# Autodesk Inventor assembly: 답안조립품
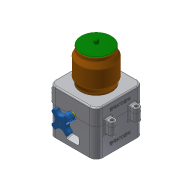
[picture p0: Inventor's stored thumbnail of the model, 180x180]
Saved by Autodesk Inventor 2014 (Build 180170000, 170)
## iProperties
Created: 2018-01
Part Number: 답안조립품
Document SubType Name: Assembly
Designer: user
Author: user
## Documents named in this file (9)
- C:\Users\user\Desktop\480108V1006\답안조립품.iam
- C:\Users\user\Desktop\480108V1006\본체.ipt
- C:\Users\user\Desktop\480108V1006\본체커버.ipt
- C:\Users\user\Desktop\480108V1006\볼트 M3x12.ipt
- C:\Users\user\Desktop\480108V1006\볼트 M4x12.ipt
- C:\Users\user\Desktop\480108V1006\용기.ipt
- C:\Users\user\Desktop\480108V1006\용기캡.ipt
- C:\Users\user\Desktop\480108V1006\핸들.ipt
- C:\Users\user\Desktop\480108V1006\핸들축.ipt
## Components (2 placed, 2 different names)
1. 핸들:1 — Mate:1, Mate:2, Mate:3, Insert:1
2. 핸들축:1 — Mate:1, Mate:2, Mate:3, Insert:4
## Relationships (5: Mate 3, Insert 2)
- Mate:1: 핸들:1 ↔ 핸들축:1
- Mate:2: 핸들:1 ↔ 핸들축:1
- Mate:3: 핸들:1 ↔ 핸들축:1
- Insert:1: 핸들:1
- Insert:4: 핸들축:1
